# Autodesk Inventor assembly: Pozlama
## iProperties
Created: 2006-07
Part Number: Pozlama
Document SubType Name: Assembly
Designer: rollin42
Part Number: Lubricant Oil
Material: Default
Author: rollin42
